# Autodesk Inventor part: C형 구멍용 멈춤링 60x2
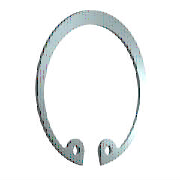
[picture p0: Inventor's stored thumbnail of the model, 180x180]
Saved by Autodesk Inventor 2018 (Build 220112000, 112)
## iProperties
IsCustomPart: 1
Created: 2012-02
Part Number: C형 구멍용 멈춤링 60x2
Material: 강철, 연강
Description: 스프링 리테이닝 링
Document SubType Name: Modeling
Standard: JIS B 2804
Designer: mdu-01
Standards Organization: JIS
Language: ko-KR
Size Designation: 60x2
Categories: <MemberInstance><Categories><Category DisplayName="샤프트 부품" InternalName="7f7aeb1f-a693-4053-b835-cee3144e0d98" Mnemonic="SHFT"><Category DisplayName="써클립" Inter
Density: 1 g/cm^3
Appearance: 강철(1)
Author: mdu-01
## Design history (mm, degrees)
sketch "스케치1"
  geometry: L1 (0, 15.113)-(0, -73.177) reference; L2 (-45.5, 0)-(45.5, 0) reference; L3 (-4.964, 1.5)-(1.502, 1.5); L4 (0, -4)-(-5.307, -4); L5 (0, -30)-(-13.027, -58.68); L6 (-13.027, -58.68)-(-26.582, -52.523); L7 (-11.621, -55.584)-(-22.16, -50.797); L8 (-9.345, -56.618)-(-10.71, -59.623); L9 (9.345, -56.618)-(10.71, -59.623); C1 r 1.25 at (-11.621, -55.584); C2 r 1.25 at (11.621, -55.584); A1 r 27.375 centre (0, -31.375) between (16.027, -53.568) and (-16.027, -53.568); A2 r 31.5 centre (0, -30) between (10.71, -59.623) and (-10.71, -59.623); A3 r 2.5 centre (-11.621, -55.584) between (-9.345, -56.618) and (-13.092, -53.563); A4 r 2.5 centre (-14.563, -51.541) between (-16.027, -53.568) and (-13.092, -53.563); A5 r 2.5 centre (14.563, -51.541) between (13.092, -53.563) and (16.027, -53.568); A6 r 2.5 centre (11.621, -55.584) between (13.092, -53.563) and (9.345, -56.618); 3 further points
  constraints: 15 point on circle, 14 end point, 9 symmetric about line, 8 centre point, 6 tangent, 4 coincident, 4 point on line, 3 perpendicular, 1 parallel, 4 other
  dimensions: "d8" = 1.375 distance of A1.centre L5.start (= 0.25 x SRB1); "d38" = 5.5 distance between parallel lines of L4 L3 (= SRB1); "d39" = 30 distance from line of L5.start L2 (= 0.5 x WD); "d43" = 31.5 radius of A2 (= 0.5 x ND); "d45" = 3.4 distance between parallel lines of L7 L6 (= 0.5 x SRB2); "d46" = 2.5 radius of A4 (= SD5); "d47" = 10.71 distance from line of L1 L8.end (= 0.17 x ND); "d48" = 2.5 diameter of C1 (= SD5); "d49" = 2.5 radius of A3 (= SD5)
extrude "본체" new body sketch "스케치1" distance "d2" = 2 (= SD); taper "d3" = 0 deg
workaxis "Work Axis1"
workaxis "Work Axis2"
workplane "Work Plane1"
body "Solid1"
other parameters: "SD" = 2 [user parameter; used in 1 equation term], "SRB1" = 5.5 [user parameter; used in 2 equation terms], "ND" = 63 [user parameter; used in 2 equation terms], "SRB2" = 6.8 [user parameter; used in 1 equation term], "SD5" = 2.5 [user parameter; used in 3 equation terms], "d50" = 0, "d51" = 0, "d52" = 0, "d53" = 0, "WDMIN" = 58 [user parameter], "SD6" = 64.2 [user parameter]
